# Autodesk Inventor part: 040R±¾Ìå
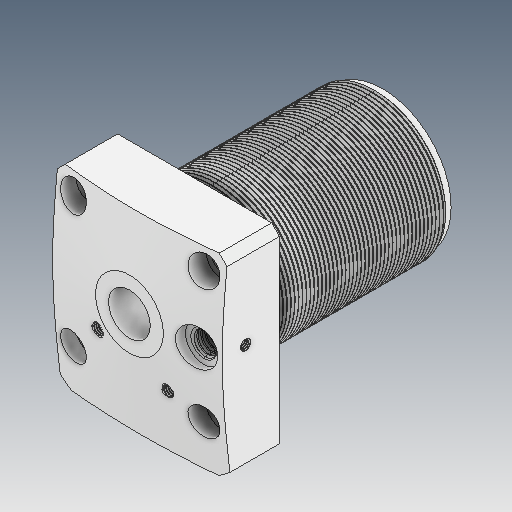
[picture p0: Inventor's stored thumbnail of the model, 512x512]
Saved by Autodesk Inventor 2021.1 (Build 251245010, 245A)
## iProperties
Created: 2021-06
Part Number: 040R±¾Ìå
Material: Ogólny
Document SubType Name: Modeling
Designer: user
Density: 1 g/cm^3
Appearance: Domyślna
Author: user
Revision Number: ÈÎºÎ
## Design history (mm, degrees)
feature "NONE"
node "Bryła1"
